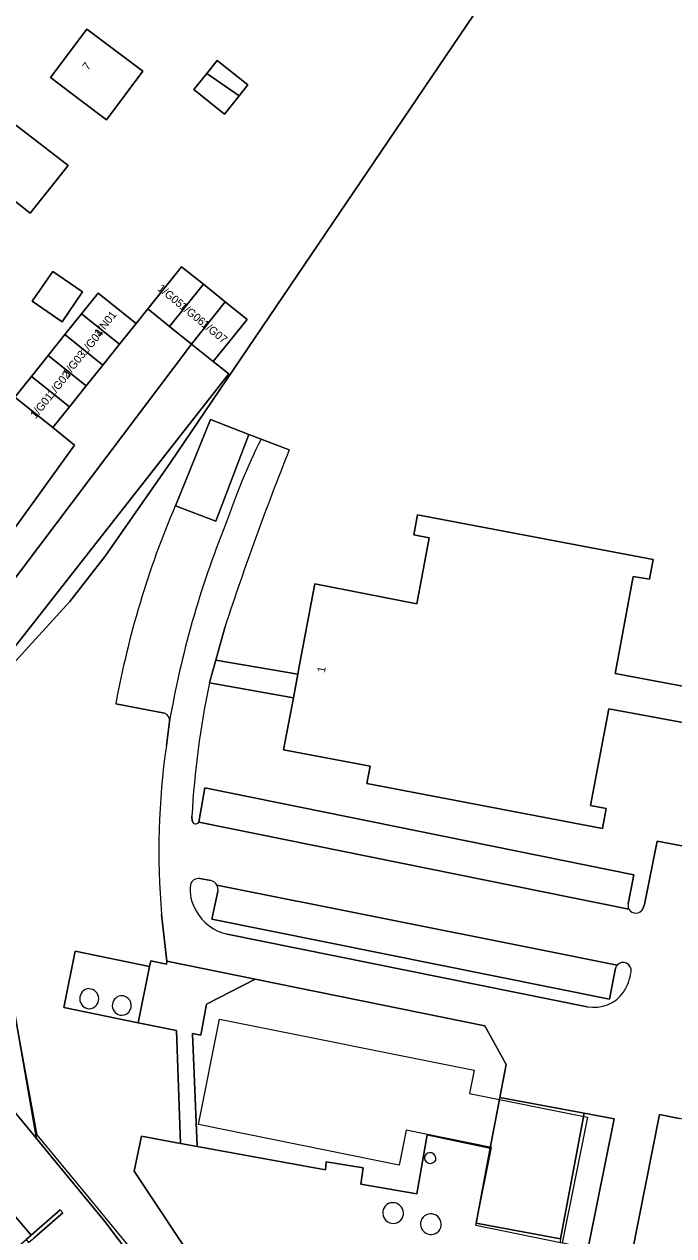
# Model space of a CAD drawing. Extents: x 158793 to 159888, y 384317 to 385256.
# Drawn here: x 159151.7 to 159232.9, y 384928.9 to 385080.3 of the extents above; entities that cross this region are included whole.
import ezdxf

# ---------------------------------------------------------------- set-up
doc = ezdxf.new("R2010")
doc.units = 0
for name, color, linetype in [('IMGEO_Berm_groen', 7, 'Continuous'), ('IMGEO_Erf', 7, 'Continuous'), ('IMGEO_Groenvoorziening', 7, 'Continuous'), ('IMGEO_Hek', 7, 'Continuous'), ('IMGEO_Muur', 7, 'Continuous'), ('IMGEO_Opslagtank', 7, 'Continuous'), ('IMGEO_Pand', 7, 'Continuous'), ('IMGEO_Pand_nummerreeks', 7, 'Continuous'), ('IMGEO_Pand_vergunning_verleend', 7, 'Continuous'), ('IMGEO_Parkeervlak_halfverhard', 7, 'Continuous'), ('IMGEO_Parkeervlak_open', 7, 'Continuous'), ('IMGEO_Rijbaan_lokaal_gesloten', 7, 'Continuous'), ('IMGEO_Rijbaan_lokaal_open', 7, 'Continuous'), ('IMGEO_Verkeerseiland_groen', 7, 'Continuous'), ('IMGEO_Voetpad_gesloten', 7, 'Continuous'), ('IMGEO_Voetpad_open', 7, 'Continuous')]:
    doc.layers.add(name, color=color, linetype=linetype)

msp = doc.modelspace()

# ---------------------------------------------------------------- linework, layer by layer
at = {"layer": 'IMGEO_Berm_groen'}
for points in [[(159216.03, 384831.72), (159205.73, 384856.1), (159199.96, 384868.91), (159197.85, 384873.25), (159190.86, 384886.66), (159185.56, 384896.09), (159179.9, 384905.24), (159170.01, 384919.82), (159161.81, 384930.66), (159155.13, 384938.75), (159153.25, 384941.03), (159148.39, 384946.91), (159144.12, 384939.38), (159143.84, 384938.9)], [(159149.25, 384932.88), (159152.61, 384928.98), (159156.21, 384932.13), (159156.55, 384931.74), (159152.96, 384928.62)]]:
    msp.add_lwpolyline(points, dxfattribs=at)
msp.add_arc((158862.95, 384689.75), 365.45, 31.9847, 41.4848, dxfattribs=at)
at = {"layer": 'IMGEO_Erf'}
for points in [[(159148.39, 384946.91), (159153.25, 384941.03), (159150.4, 384957.61), (159141, 384963.54), (159137.02, 384980.94), (159133.84, 384985.25), (159147.59, 384997.37), (159157.45, 385008.13), (159161.83, 385013.79), (159170.02, 385025.49), (159207.92, 385081.38), (159212.01, 385087.95), (159216.48, 385096.14), (159221.55, 385107.19), (159187.72, 385129.9), (159183.54, 385132.81), (159182.12, 385130.8), (159173.31, 385118.35), (159168.14, 385111.04), (159165.8, 385107.73)], [(159158.88, 385044.07), (159160.96, 385046.67), (159165.71, 385042.87), (159167.17, 385044.68), (159171.4, 385049.96), (159174.13, 385047.77), (159176.87, 385045.57), (159179.6, 385043.38), (159175.37, 385038.11), (159177.29, 385036.57), (159149.19, 385000.73), (159147.21, 385002.28), (159137.86, 384990.35), (159134.34, 384989.57), (159134.22, 384989.27), (159133.37, 384986.16), (159133.37, 384984.55), (159138.03, 384965.84), (159146.93, 384955.34), (159147.46, 384954.68)], [(159143.65, 384954.59), (159135.62, 384964.17), (159131.97, 384977.65), (159130.8, 384982.66), (159130.62, 384989.57), (159132.73, 384993.24), (159138.93, 385001.92), (159150.93, 385017.82), (159158.02, 385027.68), (159155.3, 385029.86), (159150.55, 385033.66), (159152.63, 385036.26), (159154.71, 385038.86), (159156.8, 385041.47), (159158.88, 385044.07)]]:
    msp.add_lwpolyline(points, dxfattribs=at)
for points in [[(159158.99, 385070.59), (159155, 385073.59), (159159.54, 385079.64), (159163.54, 385076.63), (159166.55, 385074.37), (159162, 385068.32)], [(159172.95, 385072.09), (159174.55, 385074.1), (159175.86, 385075.74), (159179.69, 385072.68), (159178.6, 385071.31), (159176.78, 385069.03)], [(159149.65, 385058.9), (159145.73, 385062), (159150.3, 385067.94), (159154.26, 385064.9), (159157.22, 385062.62), (159152.46, 385056.66)], [(159152.74, 385045.65), (159155.29, 385049.36), (159159.02, 385046.8), (159156.46, 385043.08)]]:
    msp.add_lwpolyline(points, close=True, dxfattribs=at)
at = {"layer": 'IMGEO_Groenvoorziening'}
for points in [[(159273.06, 385209.09), (159256.15, 385207.46), (159235.72, 385186.97), (159227.01, 385178.11), (159209.26, 385158.1), (159192.74, 385136.79), (159187.72, 385129.9), (159221.55, 385107.19), (159216.48, 385096.14), (159212.01, 385087.95), (159207.92, 385081.38), (159170.02, 385025.49), (159161.83, 385013.79), (159157.45, 385008.13), (159147.59, 384997.37), (159133.84, 384985.25), (159137.02, 384980.94), (159141, 384963.54), (159150.4, 384957.61), (159153.25, 384941.03), (159155.13, 384938.75), (159161.81, 384930.66), (159170.01, 384919.82)], [(159170.62, 385020.09), (159175.03, 385030.89), (159179.83, 385029), (159181.34, 385028.43), (159184.87, 385027.09)], [(159176.84, 385005.01), (159175.71, 385000.95), (159175.67, 385000.8), (159185.95, 384999.06), (159186.12, 385000), (159188.07, 385010.33), (159200.82, 385007.86), (159202.37, 385016.1), (159200.43, 385016.46), (159200.9, 385018.97), (159230.35, 385013.39), (159229.89, 385010.91), (159227.88, 385011.27), (159225.78, 385000), (159225.61, 384999.13), (159236.71, 384997.07)], [(159260.79, 384968.11), (159262.58, 384977.71), (159234.09, 384983.02), (159235.88, 384992.68), (159224.8, 384994.74), (159222.54, 384982.65), (159224.49, 384982.27), (159224.04, 384979.78), (159194.56, 384985.38), (159194.98, 384987.54), (159184.16, 384989.59), (159185.38, 384996.08), (159174.91, 384997.95)], [(159169.25, 384994.17), (159163.18, 384995.36)], [(159169.5, 384990.13), (159169.89, 384993.15)], [(159173.54, 384980.55), (159174.29, 384984.87), (159227.95, 384973.98), (159227.24, 384970.38)], [(159172.7, 384981.28), (159172.74, 384980.72)], [(159229.08, 384969.75), (159229.29, 384970.28), (159230.85, 384978.2), (159237.91, 384976.85), (159234.52, 384960.15)], [(159173.87, 384924.34), (159165.49, 384936.98), (159166.38, 384941.32), (159171.27, 384940.43), (159170.77, 384954.55), (159165.98, 384955.49), (159156.69, 384957.4), (159158.09, 384964.44), (159167.4, 384962.55), (159167.54, 384963.23), (159169.5, 384962.84), (159169.57, 384963.18), (159168.91, 384969.04)]]:
    msp.add_lwpolyline(points, dxfattribs=at)
for points in [[(159212, 384950.28), (159209.32, 384955.11), (159180.61, 384960.94), (159174.51, 384957.81), (159173.82, 384953.95), (159172.76, 384954.15), (159173.34, 384940.05), (159189.39, 384937.11), (159189.48, 384938.13), (159194.09, 384937.38), (159193.83, 384935.34), (159200.83, 384934.14), (159202.1, 384941.48), (159209.99, 384939.84), (159211.18, 384946.18)], [(159225.48, 384943.51), (159221.72, 384944.21), (159218.78, 384928.49), (159218.72, 384928.08), (159221.11, 384927.53), (159222.24, 384927.31), (159222.34, 384927.79)]]:
    msp.add_lwpolyline(points, close=True, dxfattribs=at)
for centre, radius, start, end in [((159526.8, 384890.23), 368.3, 158.1862, 161.8417), ((159277.53, 384974.44), 116.25, 156.8807, 169.6324), ((159278.03, 384975.79), 105.48, 167.8726, 177.0161), ((159168.95, 384993.27), 0.954, 352.6038, 71.417), ((159260.51, 384977.01), 91.95, 171.7988, 184.9744), ((159173.17, 384980.77), 0.429, 186.8724, 329.5392), ((159228.48, 384970.16), 1.26, 170.3607, 201.6308), ((159228.18, 384970.21), 1.01, 210.2041, 333.2204), ((158881.67, 384703.53), 340.6, 31.6898, 41.8304)]:
    msp.add_arc(centre, radius, start, end, dxfattribs=at)
at = {"layer": 'IMGEO_Hek'}
for points in [[(159153.36, 384941.51), (159150.4, 384957.61), (159141, 384963.54), (159137.02, 384980.94), (159133.84, 384985.25), (159147.59, 384997.37), (159157.45, 385008.13), (159161.83, 385013.79), (159170.02, 385025.49), (159207.92, 385081.38), (159212.01, 385087.95), (159216.48, 385096.14), (159221.55, 385107.19), (159187.72, 385129.9), (159192.74, 385136.79), (159209.26, 385158.1), (159227.01, 385178.11), (159235.72, 385186.97)], [(159159.29, 384934.3), (159153.36, 384941.51)], [(159225.02, 384810.15), (159206.69, 384854.26), (159201.87, 384865.3), (159196.73, 384876.23), (159192.05, 384885.46), (159189.07, 384890.75), (159181.65, 384903.16), (159173, 384916.27), (159165.46, 384926.81), (159159.29, 384934.3)]]:
    msp.add_lwpolyline(points, dxfattribs=at)
at = {"layer": 'IMGEO_Muur'}
msp.add_lwpolyline([(159152.61, 384928.98), (159151.95, 384928.41), (159152.28, 384928.03), (159152.96, 384928.62), (159156.55, 384931.74), (159156.21, 384932.13)], close=True, dxfattribs=at)
at = {"layer": 'IMGEO_Opslagtank'}
for centre, radius, start, end in [((159159.92, 384958.51), 1.26, 94.4368, 267.3464), ((159159.8, 384958.5), 1.25, 273.1678, 88.6154), ((159163.96, 384957.66), 1.22, 97.9139, 268.3072), ((159163.9, 384957.66), 1.22, 271.3401, 94.881), ((159202.51, 384938.68), 0.751, 169.8106, 332.3672), ((159202.46, 384938.53), 0.743, 344.1658, 158.012), ((159197.82, 384931.7), 1.32, 318.9835, 136.6938), ((159197.87, 384931.75), 1.32, 139.6758, 316.0015), ((159202.6, 384930.37), 1.32, 139.615, 316.0654), ((159202.55, 384930.32), 1.32, 318.9857, 136.6947)]:
    msp.add_arc(centre, radius, start, end, dxfattribs=at)
at = {"layer": 'IMGEO_Pand'}
for points in [[(159158.99, 385070.59), (159162, 385068.32), (159166.55, 385074.37), (159163.54, 385076.63), (159159.54, 385079.64), (159155, 385073.59)], [(159178.6, 385071.31), (159179.69, 385072.68), (159175.86, 385075.74), (159174.55, 385074.1)], [(159174.55, 385074.1), (159172.95, 385072.09), (159176.78, 385069.03), (159178.6, 385071.31)], [(159149.65, 385058.9), (159152.46, 385056.66), (159157.22, 385062.62), (159154.26, 385064.9), (159150.3, 385067.94), (159145.73, 385062)], [(159159.02, 385046.8), (159155.29, 385049.36), (159152.74, 385045.65), (159156.46, 385043.08)], [(159167.17, 385044.68), (159169.9, 385042.49), (159174.13, 385047.77), (159171.4, 385049.96)], [(159174.13, 385047.77), (159169.9, 385042.49), (159172.64, 385040.3), (159176.87, 385045.57)], [(159163.63, 385040.27), (159165.71, 385042.87), (159160.96, 385046.67), (159158.88, 385044.07)], [(159175.37, 385038.11), (159179.6, 385043.38), (159176.87, 385045.57), (159172.64, 385040.3)], [(159158.88, 385044.07), (159156.8, 385041.47), (159161.55, 385037.66), (159163.63, 385040.27)], [(159156.8, 385041.47), (159154.71, 385038.86), (159159.46, 385035.06), (159161.55, 385037.66)], [(159157.38, 385032.46), (159159.46, 385035.06), (159154.71, 385038.86), (159152.63, 385036.26)], [(159152.63, 385036.26), (159150.55, 385033.66), (159155.3, 385029.86), (159157.38, 385032.46)], [(159179.83, 385029), (159175.03, 385030.89), (159170.62, 385020.09), (159175.68, 385018.16)], [(159318.52, 384930.68), (159269.44, 384940.39), (159261.25, 384942.01), (159234.88, 384947.23), (159234.13, 384943.45), (159233.61, 384943.55), (159231.17, 384944.04), (159226.79, 384921.99), (159229.75, 384921.4), (159228.97, 384917.49), (159233.57, 384916.58), (159236.99, 384915.9), (159259.08, 384911.53), (159263.02, 384910.75), (159303.05, 384902.83), (159304.8, 384902.48), (159312.65, 384900.93), (159315.33, 384914.5), (159316.14, 384918.63)], [(159221.72, 384944.21), (159211.18, 384946.18), (159209.99, 384939.84), (159208.24, 384930.46), (159218.78, 384928.49)]]:
    msp.add_lwpolyline(points, close=True, dxfattribs=at)
msp.add_lwpolyline([(159236.71, 384997.07), (159225.61, 384999.13), (159225.78, 385000), (159227.88, 385011.27), (159229.89, 385010.91), (159230.35, 385013.39), (159200.9, 385018.97), (159200.43, 385016.46), (159202.37, 385016.1), (159200.82, 385007.86), (159188.07, 385010.33), (159186.12, 385000), (159185.95, 384999.06), (159185.38, 384996.08), (159184.16, 384989.59), (159194.98, 384987.54), (159194.56, 384985.38), (159224.04, 384979.78), (159224.49, 384982.27), (159222.54, 384982.65), (159224.8, 384994.74), (159235.88, 384992.68)], dxfattribs=at)
at = {"layer": 'IMGEO_Pand_vergunning_verleend'}
msp.add_lwpolyline([(159173.5, 384942.78), (159176.16, 384955.97), (159207.99, 384949.56), (159207.41, 384946.67), (159222.14, 384943.7), (159218.97, 384927.98), (159208.19, 384930.16), (159210.16, 384939.92), (159199.47, 384942.07), (159198.59, 384937.72)], close=True, dxfattribs=at)
at = {"layer": 'IMGEO_Parkeervlak_halfverhard'}
for points in [[(159227.24, 384970.38), (159227.95, 384973.98), (159174.29, 384984.87), (159173.54, 384980.55)], [(159173.54, 384980.55), (159227.31, 384969.7)], [(159225.86, 384962.7), (159216.09, 384964.66), (159175.82, 384972.7)], [(159175.93, 384971.9), (159175.2, 384968.45), (159224.89, 384958.46), (159225.67, 384962.33)]]:
    msp.add_lwpolyline(points, dxfattribs=at)
for centre, radius, start, end in [((159174.82, 384972.16), 1.14, 346.4646, 28.38), ((159228.48, 384970.16), 1.26, 170.3607, 201.6308), ((159226.63, 384962.04), 1.01, 139.2267, 162.9332)]:
    msp.add_arc(centre, radius, start, end, dxfattribs=at)
at = {"layer": 'IMGEO_Parkeervlak_open'}
msp.add_lwpolyline([(159177.29, 385036.57), (159175.37, 385038.11), (159172.64, 385040.3), (159134.34, 384989.57), (159137.86, 384990.35), (159147.21, 385002.28), (159149.19, 385000.73)], close=True, dxfattribs=at)
for points in [[(159181.34, 385028.43), (159179.83, 385029), (159175.68, 385018.16), (159170.62, 385020.09)], [(159163.18, 384995.36), (159169.25, 384994.17)]]:
    msp.add_lwpolyline(points, dxfattribs=at)
for centre, radius, start, end in [((159262.66, 384988.41), 90.64, 153.798, 161.1237), ((159277.53, 384974.44), 116.25, 156.8807, 169.6324), ((159287.74, 384972.84), 119.58, 157.9506, 170.2221), ((159168.95, 384993.27), 0.954, 352.6038, 71.417)]:
    msp.add_arc(centre, radius, start, end, dxfattribs=at)
at = {"layer": 'IMGEO_Rijbaan_lokaal_gesloten'}
msp.add_lwpolyline([(159145.65, 384929.57), (159148.94, 384925.78), (159149.53, 384926.28), (159151.95, 384928.41), (159152.61, 384928.98), (159149.25, 384932.88)], dxfattribs=at)
at = {"layer": 'IMGEO_Rijbaan_lokaal_open'}
for points in [[(159172.64, 385040.3), (159169.9, 385042.49), (159167.17, 385044.68), (159165.71, 385042.87), (159163.63, 385040.27), (159161.55, 385037.66), (159159.46, 385035.06), (159157.38, 385032.46), (159155.3, 385029.86), (159158.02, 385027.68), (159150.93, 385017.82), (159138.93, 385001.92), (159132.73, 384993.24), (159130.62, 384989.57), (159130.8, 384982.66), (159131.97, 384977.65), (159135.62, 384964.17), (159143.65, 384954.59)], [(159147.46, 384954.68), (159146.93, 384955.34), (159138.03, 384965.84), (159133.37, 384984.55), (159133.37, 384986.16), (159134.22, 384989.27), (159134.34, 384989.57), (159172.64, 385040.3)], [(159184.87, 385027.09), (159181.34, 385028.43)], [(159174.91, 384997.95), (159174.95, 384998.15), (159175.67, 385000.8), (159175.71, 385000.95), (159176.84, 385005.01)], [(159169.89, 384993.15), (159169.5, 384990.13)], [(159172.74, 384980.72), (159172.7, 384981.28)], [(159227.31, 384969.7), (159173.54, 384980.55)], [(159237.91, 384976.85), (159230.85, 384978.2), (159229.29, 384970.28), (159229.08, 384969.75)], [(159173.68, 384973.54), (159175.05, 384973.27)], [(159175.82, 384972.7), (159216.09, 384964.66), (159225.86, 384962.7)], [(159168.91, 384969.04), (159169.57, 384963.18), (159180.61, 384960.94), (159209.32, 384955.11), (159212, 384950.28), (159211.18, 384946.18), (159221.72, 384944.21), (159225.48, 384943.51), (159222.34, 384927.79)], [(159222.13, 384957.5), (159177.12, 384966.56)], [(159226.79, 384921.99), (159231.17, 384944.04), (159233.61, 384943.55)], [(159218.78, 384928.49), (159208.24, 384930.46), (159209.99, 384939.84), (159202.1, 384941.48), (159200.83, 384934.14), (159193.83, 384935.34), (159194.09, 384937.38), (159189.48, 384938.13), (159189.39, 384937.11), (159173.34, 384940.05), (159171.27, 384940.43), (159166.38, 384941.32), (159165.49, 384936.98), (159173.87, 384924.34)]]:
    msp.add_lwpolyline(points, dxfattribs=at)
for centre, radius, start, end in [((159262.66, 384988.41), 90.64, 153.798, 161.1237), ((159526.8, 384890.23), 368.3, 158.1862, 161.8417), ((159287.74, 384972.84), 119.58, 157.9506, 170.2221), ((159278.03, 384975.79), 105.48, 167.8726, 177.0161), ((159260.51, 384977.01), 91.95, 171.7988, 184.9744), ((159173.17, 384980.77), 0.429, 186.8724, 329.5392), ((159173.59, 384972.39), 1.15, 85.6527, 161.7945), ((159177.34, 384972.11), 4.88, 172.364, 212.6419), ((159174.83, 384972.17), 1.13, 28.4493, 78.7921), ((159178.44, 384972.39), 5.98, 209.2725, 257.275), ((159228.18, 384970.21), 1.01, 210.2041, 333.2204), ((159226.62, 384962.05), 0.993, 349.7074, 139.1422), ((159221.33, 384962.7), 6.32, 327.5778, 352.4055), ((159222.97, 384961.98), 4.55, 259.4241, 324.2006), ((159202.51, 384938.68), 0.751, 169.8106, 332.3672), ((159202.46, 384938.53), 0.743, 344.1658, 158.012), ((159197.82, 384931.7), 1.32, 318.9835, 136.6938), ((159197.87, 384931.75), 1.32, 139.6758, 316.0015), ((159202.6, 384930.37), 1.32, 139.615, 316.0654), ((159202.55, 384930.32), 1.32, 318.9857, 136.6947)]:
    msp.add_arc(centre, radius, start, end, dxfattribs=at)
at = {"layer": 'IMGEO_Verkeerseiland_groen'}
for points in [[(159175.05, 384973.27), (159173.68, 384973.54)], [(159175.2, 384968.45), (159175.93, 384971.9)], [(159225.67, 384962.33), (159224.89, 384958.46), (159175.2, 384968.45)], [(159177.12, 384966.56), (159222.13, 384957.5)]]:
    msp.add_lwpolyline(points, dxfattribs=at)
for centre, radius, start, end in [((159173.59, 384972.39), 1.15, 85.6527, 161.7945), ((159177.34, 384972.11), 4.88, 172.364, 212.6419), ((159174.83, 384972.17), 1.13, 28.4493, 78.7921), ((159174.82, 384972.16), 1.14, 346.4646, 28.38), ((159178.44, 384972.39), 5.98, 209.2725, 257.275), ((159226.62, 384962.05), 0.993, 349.7074, 139.1422), ((159226.63, 384962.04), 1.01, 139.2267, 162.9332), ((159221.33, 384962.7), 6.32, 327.5778, 352.4055), ((159222.97, 384961.98), 4.55, 259.4241, 324.2006)]:
    msp.add_arc(centre, radius, start, end, dxfattribs=at)
at = {"layer": 'IMGEO_Voetpad_gesloten'}
msp.add_lwpolyline([(159167.4, 384962.55), (159158.09, 384964.44), (159156.69, 384957.4), (159165.98, 384955.49)], close=True, dxfattribs=at)
for centre, radius, start, end in [((159159.92, 384958.51), 1.26, 94.4368, 267.3464), ((159159.8, 384958.5), 1.25, 273.1678, 88.6154), ((159163.96, 384957.66), 1.22, 97.9139, 268.3072), ((159163.9, 384957.66), 1.22, 271.3401, 94.881), ((158862.95, 384689.75), 365.45, 31.9847, 41.4848), ((158881.67, 384703.53), 340.6, 31.6898, 41.8304)]:
    msp.add_arc(centre, radius, start, end, dxfattribs=at)
at = {"layer": 'IMGEO_Voetpad_open'}
for points in [[(159185.95, 384999.06), (159175.67, 385000.8), (159174.95, 384998.15), (159174.91, 384997.95), (159185.38, 384996.08)], [(159180.61, 384960.94), (159169.57, 384963.18), (159169.5, 384962.84), (159167.54, 384963.23), (159167.4, 384962.55), (159165.98, 384955.49), (159170.77, 384954.55), (159171.27, 384940.43), (159173.34, 384940.05), (159172.76, 384954.15), (159173.82, 384953.95), (159174.51, 384957.81)]]:
    msp.add_lwpolyline(points, close=True, dxfattribs=at)

# ---------------------------------------------------------------- texts
at = {"layer": 'IMGEO_Pand_nummerreeks'}
for s, rotation, p in [('7', 53.0361, (159159.72, 385074.42)), ('1/G05', 320.7883, (159168.31, 385047.08)), ('1/G06', 320.7883, (159171.05, 385044.84)), ('1/N01', 51.6486, (159161.13, 385041.14)), ('1/G07', 320.7883, (159173.79, 385042.6)), ('1/G04', 51.2987, (159159.42, 385038.82)), ('1/G03', 51.2987, (159157.21, 385036.12)), ('1/G02', 51.2987, (159155.31, 385033.58)), ('1/G01', 51.2987, (159153.15, 385030.88)), ('1', 79.326, (159189.31, 384999.19))]:
    msp.add_text(s, height=1, rotation=rotation, dxfattribs=at).set_placement(p)

doc.saveas('drawing.dxf')
